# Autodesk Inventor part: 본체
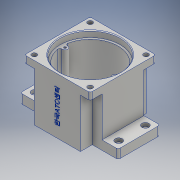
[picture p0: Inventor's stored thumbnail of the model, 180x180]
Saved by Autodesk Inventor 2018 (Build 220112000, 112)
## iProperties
Created: 2020-07
Part Number: 본체
Material: 알루미늄 6061
Document SubType Name: Modeling
Designer: Admin
Density: 2.7 g/cm^3
Appearance: 알루미늄 - 평지
Author: Admin
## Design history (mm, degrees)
sketch "스케치1"
  geometry: L1 (-98, 0)-(98, 0) reference; L2 (0, -65.8)-(0, 65.8) reference; L3 (-70, 0)-(-70, 30); L4 (-70, 30)-(-33, 30); L5 (-33, 30)-(-33, 47); L6 (-33, 47)-(0, 47); L7 (98, 0)-(-98, 0); L8 (70, 0)-(70, 30); L9 (70, 30)-(33, 30); L10 (33, 30)-(33, 47); L11 (33, 47)-(0, 47); L12 (0, 65.8)-(0, -65.8); L13 (-70, 0)-(-70, -30); L14 (-70, -30)-(-33, -30); L15 (-33, -30)-(-33, -47); L16 (-33, -47)-(0, -47); L17 (70, 0)-(70, -30); L18 (70, -30)-(33, -30); L19 (33, -30)-(33, -47); L20 (33, -47)-(0, -47); 1 further point
  constraints: 36 end point, 15 symmetric about line, 4 point on line, 3 perpendicular, 1 vertical
  dimensions: "d0" = 66 distance between parallel lines of L10 L5; "d1" = 140 distance between parallel lines of L17 L13; "d2" = 60 distance between parallel lines of L18 L9; "d3" = 94 distance between parallel lines of L20 L11
extrude "돌출1" new body sketch "스케치1" distance "d4" = 13; taper "d5" = 0 deg
sketch "스케치2"
  geometry: 1 further point
sketch "스케치3"
  geometry: L1 (33, 47)-(33, 30) reference; L2 (-33, -47)-(33, -47); L3 (33, -47)-(33, 47); L4 (33, 47)-(-33, 47); L5 (-33, 47)-(-33, -47); L6 (-33, -47)-(33, 47); L7 (33, -47)-(-33, 47); L8 (33, 30)-(70, 30) reference; L9 (33, -30)-(70, -30) reference; L10 (33, 30)-(47, 30); L11 (47, 30)-(47, -30); L12 (47, -30)-(33, -30); L13 (33, -30)-(33, 30); L14 (0, -65.8)-(0, 65.8) reference; L15 (-33, 47)-(-33, 30); L16 (33, -47)-(-33, -47); L17 (-33, -47)-(-33, 47); L18 (-33, -47)-(33, 47); L19 (-33, 30)-(-47, 30); L20 (-33, -30)-(-47, -30); L21 (-33, 30)-(-47, 30); L22 (-47, 30)-(-47, -30); L23 (-47, -30)-(-33, -30); L24 (-33, -30)-(-33, 30); 3 further points
  constraints: 40 end point, 11 symmetric about line, 4 parallel, 2 horizontal, 2 midpoint, 2 perpendicular, 1 point on line
  dimensions: "d6" = 14 distance between parallel lines of L3 L11
extrude "돌출2" join sketch "스케치3" distance "d7" = 57; taper "d8" = 0 deg
sketch "스케치4"
  geometry: L1 (-47, -47)-(47, -47); L2 (47, -47)-(47, 47); L3 (47, 47)-(-47, 47); L4 (-47, 47)-(-47, -47); L5 (-47, -47)-(47, 47); L6 (47, -47)-(-47, 47); 1 further point
  constraints: 12 end point, 2 midpoint, 2 parallel, 1 horizontal, 1 perpendicular
  dimensions: "d9" = 94 distance of L3.end L2.end; "d10" = 94 distance of L1.end L2.end
extrude "돌출3" join sketch "스케치4" distance "d11" = 10; taper "d12" = 0 deg
sketch "스케치5"
  geometry: L1 (98, 0)-(-98, 0) reference; L2 (0, -65.8)-(0, 65.8) reference; C1 r 27.5 at (0, -11); 1 further point
  constraints: 1 centre point, 1 point on line
  dimensions: "d13" = 55 diameter of C1; "d14" = 11 distance from line of L1 C1.centre
extrude "돌출4" join sketch "스케치5" distance "d15" = 7; taper "d16" = 0 deg
sketch "스케치6"
  geometry: C1 r 43 at (0, 0); 1 further point
  constraints: 1 centre point, 1 coincident
  dimensions: "d17" = 86 diameter of C1
extrude "돌출5" cut sketch "스케치6" distance "d18" = 9; taper "d19" = 0 deg
sketch "스케치7" dims "d22" = 72
  geometry: L1 (0, -65.8)-(0, 65.8) reference; L2 (-137.2, 0)-(137.2, 0) reference; L3 (137.2, 0)-(-137.2, 0); C1 r 43 at (0, 0); A1 r 40 centre (0, 0) between (39.29, 7.503) and (-39.29, 7.503); A2 r 4 centre (36, 0) between (36.615, 3.952) and (36.615, -3.952); A3 r 3 centre (36.343, -6.94) between (39.29, -7.503) and (35.778, -3.994); A4 r 3 centre (36.343, 6.94) between (35.778, 3.994) and (39.29, 7.503); A5 r 4 centre (-36, 0) between (-36.615, -3.952) and (-36.615, 3.952); A6 r 3 centre (-36.343, -6.94) between (-35.778, -3.994) and (-39.29, -7.503); A7 r 3 centre (-36.343, 6.94) between (-39.29, 7.503) and (-35.778, 3.994); A8 r 40 centre (0, 0) between (-39.29, -7.503) and (39.29, -7.503); A9 r 40 centre (0, 0) between (-39.29, 7.503) and (-39.29, -7.503); 2 further points
  constraints: 24 point on circle, 14 symmetric about line, 10 centre point, 3 coincident, 2 end point, 2 point on line, 2 tangent, 1 vertical, 10 other
  dimensions: "d20" = 80 diameter of A1; "d21" = 86 diameter of C1; "d23" = 8 diameter of A2; "d24" = 3 radius of A3
extrude "돌출6" cut sketch "스케치7" distance "d25" = 62; taper "d26" = 0 deg
sketch "스케치8"
  geometry: L1 (0, -65.8)-(0, 65.8) reference; L2 (-98, 0)-(98, 0) reference; C1 r 21 at (0, -11); C2 r 15 at (0, 20); 1 further point
  constraints: 2 centre point, 2 point on line
  dimensions: "d27" = 42 diameter of C1; "d28" = 30 diameter of C2; "d29" = 11 distance from line of L2 C1.centre; "d30" = 20 distance from line of L2 C2.centre
extrude "돌출7" join sketch "스케치8" distance "d31" = 7; taper "d32" = 0 deg
sketch "스케치9"
  geometry: C1 r 17.5 at (0, -11); A1 r 21 centre (0, -11) between (-8.978, 7.984) and (8.978, 7.984) reference; A2 r 15 centre (0, 20) between (8.978, 7.984) and (-8.978, 7.984) reference; 1 further point
  constraints: 1 centre point, 1 coincident
  dimensions: "d33" = 35 diameter of C1
extrude "돌출8" cut sketch "스케치9" distance "d34" = 10; taper "d35" = 0 deg
sketch "스케치10"
  geometry: C1 r 17.5 at (0, 0) reference; C2 r 12.5 at (0, 0); 1 further point
  constraints: 1 centre point, 1 coincident
  dimensions: "d36" = 25 diameter of C2
extrude "돌출9" cut sketch "스케치10" distance "d37" = 4.7; taper "d38" = 0 deg
sketch "스케치11"
  geometry: C1 r 12.5 at (0, 0) reference; C2 r 16 at (0, 0); 1 further point
  constraints: 1 centre point, 1 coincident
  dimensions: "d39" = 32 diameter of C2
extrude "돌출10" cut sketch "스케치11" distance "d40" = 8.3; taper "d41" = 0 deg
sketch "스케치12"
  geometry: C1 r 17.5 at (0, -11) reference; C2 r 11 at (0, 20); A1 r 21 centre (0, -11) between (-8.978, 7.984) and (8.978, 7.984) reference; A2 r 15 centre (0, 20) between (8.978, 7.984) and (-8.978, 7.984) reference; 1 further point
  constraints: 1 centre point, 1 coincident
  dimensions: "d42" = 22 diameter of C2
extrude "돌출11" cut sketch "스케치12" distance "d43" = 7; taper "d44" = 0 deg
sketch "스케치13"
  geometry: C1 r 27.5 at (0, -31) reference; C2 r 11 at (0, 0) reference; C3 r 9.5 at (0, 0); 1 further point
  constraints: 1 centre point, 1 coincident
  dimensions: "d45" = 19 diameter of C3
extrude "돌출12" cut sketch "스케치13" distance "d46" = 3; taper "d47" = 0 deg
sketch "스케치15"
  geometry: L1 (47, 30)-(47, -30) reference; L2 (47, -30)-(70, -30) reference; L3 (70, -30)-(70, 30) reference; L4 (70, 30)-(47, 30) reference; L5 (0, -65.8)-(0, 65.8) reference; L6 (-98, 0)-(98, 0) reference; 3 further points
  dimensions: "d52" = 11 distance from line of L4 point (60, 19); "d53" = 10 distance from line of L3 point (60, 19); "d54" = 10 distance from line of L3 point (60, -19); "d55" = 11 distance from line of L2 point (60, -19)
hole "구멍1" sketch "스케치15" at (60, 19), (60, -19) diameter "d56" = 4.5; stored, may be unused: countersink angle "d60" = 90 deg, drill point angle "d62" = 0 deg; dims "d57" = 6, "d58" = 10, "d59" = 5, "d61" = 8
sketch "스케치16"
  geometry: C1 r 43 at (0, 0) reference; A1 r 4 centre (36, 0) between (36.615, 3.952) and (36.615, -3.952) reference; A2 r 3 centre (36.343, -6.94) between (39.29, -7.503) and (36.615, -3.952) reference; A3 r 40 centre (0, 0) between (-39.29, -7.503) and (39.29, -7.503) reference; A4 r 3 centre (-36.343, -6.94) between (-36.615, -3.952) and (-39.29, -7.503) reference; A5 r 4 centre (-36, 0) between (-36.615, -3.952) and (-36.615, 3.952) reference; A6 r 3 centre (-36.343, 6.94) between (-39.29, 7.503) and (-36.615, 3.952) reference; A7 r 40 centre (0, 0) between (39.29, 7.503) and (-39.29, 7.503) reference; A8 r 3 centre (36.343, 6.94) between (36.615, 3.952) and (39.29, 7.503) reference; 3 further points
  constraints: 2 coincident
hole "구멍2" sketch "스케치16" at (36, 0), (-36, 0) diameter "d63" = 3.242; stored, may be unused: countersink angle "d67" = 90 deg, drill point angle "d69" = 0 deg; dims "d64" = 7, "d65" = 10, "d66" = 5, "d68" = 9
fillet "모깎기1" dims "d70" = 3
sketch "스케치18"
  geometry: L1 (-47, 44)-(-47, -44) reference; L2 (-44, -47)-(44, -47) reference; L3 (47, -44)-(47, 44) reference; L4 (44, 47)-(-44, 47) reference; L5 (0, -66.67)-(0, 66.67) reference; L6 (-98, 0)-(98, 0) reference; C1 r 43 at (0, 0) reference; A1 r 3 centre (-44, 44) between (-44, 47) and (-47, 44) reference; A2 r 3 centre (-44, -44) between (-47, -44) and (-44, -47) reference; A3 r 3 centre (44, -44) between (44, -47) and (47, -44) reference; A4 r 3 centre (44, 44) between (47, 44) and (44, 47) reference; 5 further points
  dimensions: "d71" = 7 distance from line of L3 point (40, -40); "d72" = 7 distance from line of L1 point (-40, -40); "d73" = 7 distance from line of L3 point (40, 40); "d74" = 7 distance from line of L1 point (-40, 40); "d75" = 7 distance from line of L2 point (40, -40); "d76" = 7 distance from line of L2 point (-40, -40); "d77" = 7 distance from line of L4 point (-40, 40); "d78" = 7 distance from line of L4 point (40, 40)
hole "구멍3" sketch "스케치18" at (40, -40), (-40, -40), (-40, 40), (40, 40) diameter "d79" = 7; stored, may be unused: countersink angle "d83" = 90 deg, drill point angle "d85" = 0 deg; dims "d80" = 7, "d81" = 10, "d82" = 5, "d84" = 10
sketch "스케치19"
  geometry: L1 (-11, 80)-(77, 80) reference; L2 (66, 0)-(0, 0) reference; 3 further points
  constraints: 1 midpoint, 1 vertical alignment, 1 other
  dimensions: "d86" = 40 distance from line of L1 point (33, 40)
feature "엠보싱1" sketch "스케치19" dims "d0" = 66, "d1" = 140, "d2" = 60, "d3" = 94, "d87" = 0.5, "d88" = 0
fillet "모깎기2" dims "d89" = 3
chamfer "모따기1" distance "d90" = 0.8; stored, may be unused: second distance "d91" = 2, angle "d92" = 30 deg
chamfer "모따기2" distance "d93" = 1; stored, may be unused: second distance "d94" = 2, angle "d95" = 30 deg
fillet "모깎기3" dims "d96" = 3
chamfer "모따기3" distance "d97" = 1; stored, may be unused: second distance "d98" = 2, angle "d99" = 30 deg
node "솔리드1"
mirror "미러1"
node "투영된 루프1"
node "투영된 루프2"
node "투영된 루프3"
node "투영된 루프4"
node "투영된 루프5"
node "투영된 루프7"
node "투영된 루프8"
node "투영된 루프9"
